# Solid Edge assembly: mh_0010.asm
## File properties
Title: grip_unit
Author: edge
Template: normal.asm
Last saved by: edge
Revision: 46
Application: Solid Edge
Username: kiyo
文書内容のタイプ: 1
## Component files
mh_0013.asm
mh_0021.par
mh_0020.par
mh_0032.par
mh_0014.asm
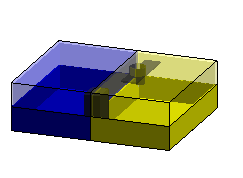
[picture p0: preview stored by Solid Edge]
